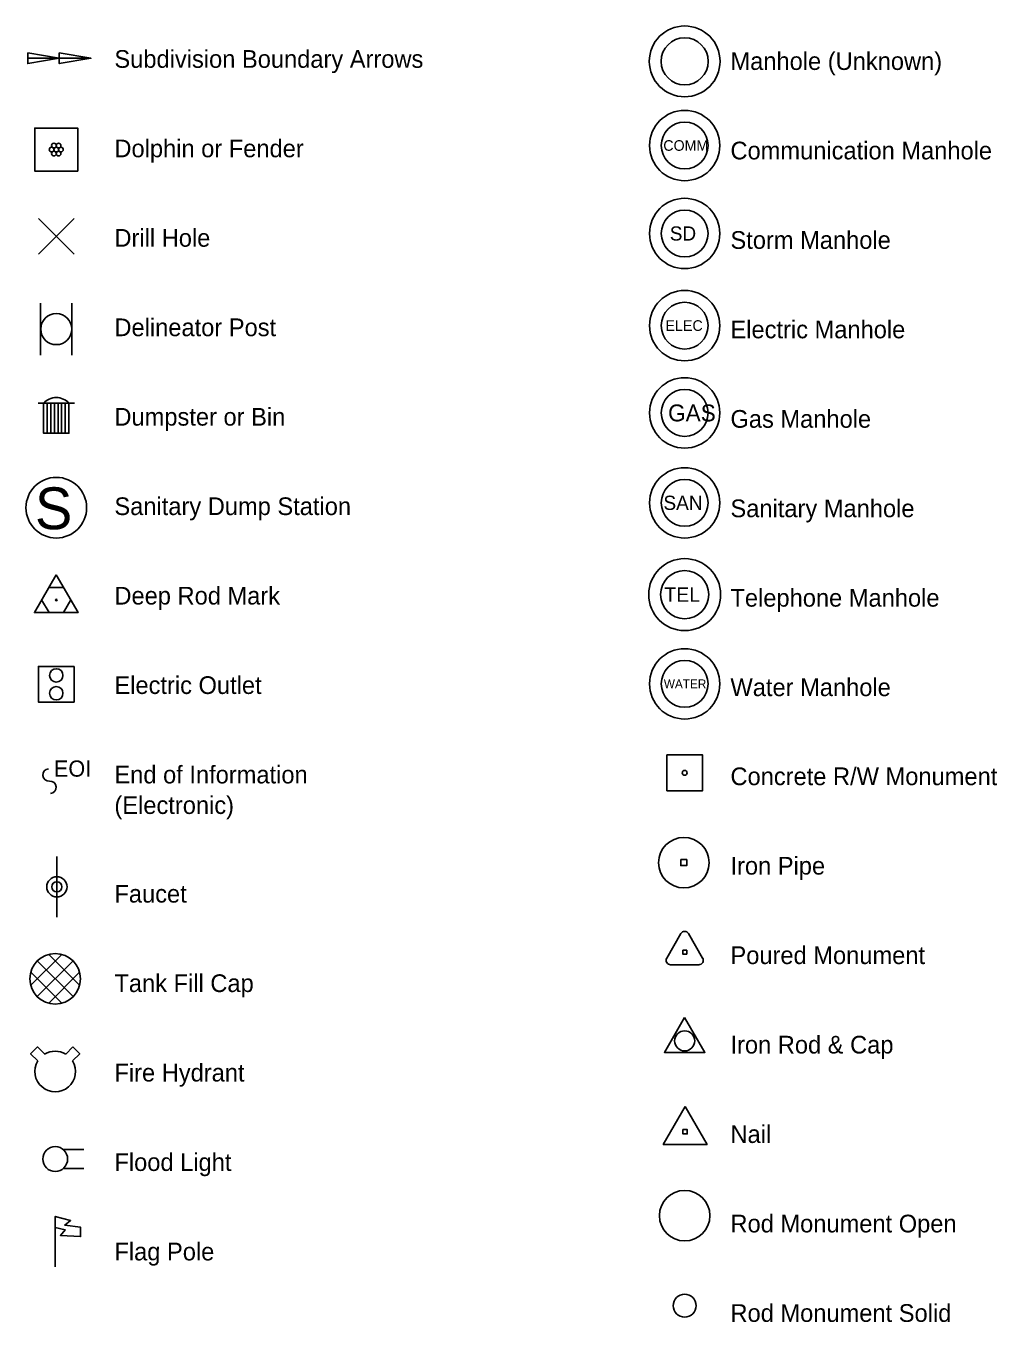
# Model space of a CAD drawing. Extents: x -371 to 730, y -9 to 425.
# Drawn here: x -370.9 to -274.8, y 166.6 to 294.8 of the extents above; entities that cross this region are included whole.
import ezdxf

# ---------------------------------------------------------------- set-up
doc = ezdxf.new("R2010")
doc.units = 0
for name, color, linetype in [('DelineatorPost_ep', 7, 'Continuous'), ('Dolphins_ep', 7, 'Continuous'), ('FireHydrant_ep', 7, 'Continuous'), ('FloodLight_ep', 7, 'Continuous'), ('ManholeCover_ep', 7, 'Continuous'), ('ManholeCovUnk_ep', 7, 'Continuous'), ('ManholeCovW_ep', 7, 'Continuous'), ('ManholeElec_ep', 7, 'Continuous'), ('ManholeGas_ep', 7, 'Continuous'), ('ManholeSS_ep', 7, 'Continuous'), ('ManholeSW_ep', 7, 'Continuous'), ('ManholeTel_ep', 7, 'Continuous'), ('MiscEquip_ep', 7, 'Continuous'), ('Monument_ep', 7, 'Continuous'), ('PowerElecOut_ep', 7, 'Continuous'), ('SanitaryDumpSta_ep', 7, 'Continuous'), ('SU_Misc_ep', 7, 'Continuous'), ('TankUG_ep', 7, 'Continuous'), ('Trash_ep', 7, 'Continuous'), ('WaterMisc_ep', 7, 'Continuous')]:
    doc.layers.add(name, color=color, linetype=linetype)

# ---------------------------------------------------------------- blocks, each defined once
blk = doc.blocks.new('DblArrow')
blk.add_line((0, 0), (-1, 0))
for points in [[(-1, 0.083), (-0.5, 0), (-1, -0.084)], [(-0.5, 0.083), (0, 0), (-0.5, -0.084)]]:
    blk.add_lwpolyline(points, close=True)
blk = doc.blocks.new('EOI')
at = {"layer": 'SU_Misc_ep'}
for centre, start, end in [((-0.05, 0.61), 95, 275), ((0.05, -0.61), 275, 95)]:
    blk.add_arc(centre, 0.613, start, end, dxfattribs=at)
blk.add_text('EOI', height=1.6, dxfattribs=at).set_placement((0.44, 0.44))

msp = doc.modelspace()

# ---------------------------------------------------------------- linework, layer by layer
for centre in [(-368.34, 282.61), (-368.11, 283.01), (-368.11, 282.21), (-367.64, 283.01), (-367.64, 282.21), (-367.41, 282.61)]:
    msp.add_circle(centre, 0.231)
at = {"layer": 'DelineatorPost_ep'}
for p, q in [((-369.42, 262.28), (-369.42, 267.42)), ((-366.33, 262.28), (-366.33, 267.42))]:
    msp.add_line(p, q, dxfattribs=at)
msp.add_circle((-367.87, 264.85), 1.54, dxfattribs=at)
at = {"layer": 'Dolphins_ep'}
msp.add_lwpolyline([(-365.75, 280.49), (-365.75, 284.73), (-370, 284.73), (-370, 280.49)], close=True, dxfattribs=at)
msp.add_circle((-367.87, 282.61), 0.231, dxfattribs=at)
at = {"layer": 'FireHydrant_ep'}
for points in [[(-369.02, 193.12), (-369.74, 193.83), (-370.41, 193.16), (-369.69, 192.44)], [(-366.22, 193.83), (-366.93, 193.12)], [(-366.26, 192.44), (-365.55, 193.16), (-366.22, 193.83)]]:
    msp.add_lwpolyline(points, dxfattribs=at)
for start, end in [(148.7002, 31.2998), (58.7002, 121.2998)]:
    msp.add_arc((-367.98, 191.4), 2.01, start, end, dxfattribs=at)
at = {"layer": 'FloodLight_ep'}
for p, q in [((-367.18, 183.68), (-365.13, 183.68)), ((-367.18, 181.81), (-365.13, 181.81))]:
    msp.add_line(p, q, dxfattribs=at)
msp.add_circle((-367.98, 182.74), 1.23, dxfattribs=at)
at = {"layer": 'ManholeCover_ep'}
for radius in [3.48, 2.32]:
    msp.add_circle((-305.7, 283.01), radius, dxfattribs=at)
at = {"layer": 'ManholeCovUnk_ep'}
for radius in [3.5, 2.33]:
    msp.add_circle((-305.7, 291.34), radius, dxfattribs=at)
at = {"layer": 'ManholeCovW_ep'}
for radius in [3.48, 2.32]:
    msp.add_circle((-305.7, 229.75), radius, dxfattribs=at)
at = {"layer": 'ManholeElec_ep'}
for radius in [3.48, 2.32]:
    msp.add_circle((-305.7, 265.19), radius, dxfattribs=at)
at = {"layer": 'ManholeGas_ep'}
for radius in [3.48, 2.32]:
    msp.add_circle((-305.7, 256.56), radius, dxfattribs=at)
at = {"layer": 'ManholeSS_ep'}
for radius in [3.48, 2.32]:
    msp.add_circle((-305.7, 247.66), radius, dxfattribs=at)
at = {"layer": 'ManholeSW_ep'}
for radius in [3.48, 2.32]:
    msp.add_circle((-305.7, 274.31), radius, dxfattribs=at)
at = {"layer": 'ManholeTel_ep'}
for radius in [3.56, 2.38]:
    msp.add_circle((-305.7, 238.58), radius, dxfattribs=at)
at = {"layer": 'MiscEquip_ep'}
msp.add_lwpolyline([(-367.98, 172.06), (-367.98, 177.06), (-366.45, 176.66), (-367.04, 176.2), (-365.48, 176), (-365.46, 175.07), (-367.46, 175.19), (-366.99, 175.72), (-367.98, 175.98)], dxfattribs=at)
at = {"layer": 'Monument_ep'}
for p, q in [((-369.63, 272.27), (-366.11, 275.8)), ((-366.11, 272.27), (-369.63, 275.8)), ((-367.15, 239.3), (-368.6, 239.3)), ((-369.32, 238.05), (-368.59, 236.8)), ((-367.16, 236.8), (-366.43, 238.06))]:
    msp.add_line(p, q, dxfattribs=at)
for points in [[(-367.87, 240.55), (-370.04, 236.8), (-365.71, 236.8)], [(-307.46, 222.72), (-307.46, 219.18), (-303.93, 219.18), (-303.93, 222.72)], [(-306.08, 212.36), (-306.08, 211.77), (-305.49, 211.77), (-305.49, 212.36)], [(-305.89, 203.4), (-305.89, 203.01), (-305.5, 203.01), (-305.5, 203.4)], [(-305.7, 196.74), (-307.7, 193.28), (-303.7, 193.28)], [(-305.66, 187.94), (-307.82, 184.19), (-303.49, 184.19)], [(-305.88, 185.66), (-305.88, 185.22), (-305.44, 185.22), (-305.44, 185.66)]]:
    msp.add_lwpolyline(points, close=True, dxfattribs=at)
for points in [[(-306.08, 205.04), (-307.48, 202.62)], [(-303.92, 202.62), (-305.31, 205.04)], [(-307.09, 201.96), (-304.3, 201.96)]]:
    msp.add_lwpolyline(points, dxfattribs=at)
for centre, radius in [((-367.87, 238.05), 0.0873), ((-305.7, 220.95), 0.236), ((-305.78, 212.06), 2.5), ((-305.7, 194.43), 0.99), ((-305.7, 177.14), 2.5)]:
    msp.add_circle(centre, radius, dxfattribs=at)
for centre, radius, start, end in [((-305.7, 204.82), 0.444, 30, 150), ((-307.09, 202.4), 0.444, 150, 270), ((-304.3, 202.4), 0.444, 270, 30), ((-305.7, 168.23), 1.13, 0, 180), ((-305.7, 168.23), 1.13, 180, 0)]:
    msp.add_arc(centre, radius, start, end, dxfattribs=at)
at = {"layer": 'PowerElecOut_ep'}
msp.add_lwpolyline([(-366.11, 231.48), (-369.64, 231.48), (-369.64, 227.94), (-366.11, 227.94)], close=True, dxfattribs=at)
for centre in [(-367.87, 230.59), (-367.87, 228.82)]:
    msp.add_circle(centre, 0.663, dxfattribs=at)
at = {"layer": 'SanitaryDumpSta_ep'}
msp.add_circle((-367.87, 247.18), 3, dxfattribs=at)
at = {"layer": 'TankUG_ep'}
for p, q in [((-370.39, 199.93), (-367.33, 202.99)), ((-365.56, 199.93), (-368.62, 202.99)), ((-366.21, 198.81), (-369.75, 202.34)), ((-369.75, 198.81), (-366.21, 202.34)), ((-367.33, 198.16), (-370.39, 201.22)), ((-368.62, 198.16), (-365.56, 201.22))]:
    msp.add_line(p, q, dxfattribs=at)
msp.add_circle((-367.98, 200.57), 2.5, dxfattribs=at)
at = {"layer": 'Trash_ep'}
for points in [[(-369.67, 257.51), (-366.07, 257.51)], [(-366.62, 257.51), (-366.62, 254.55), (-369.13, 254.55), (-369.13, 257.51)], [(-368.77, 254.55), (-368.77, 257.51)], [(-368.41, 254.55), (-368.41, 257.51)], [(-368.05, 254.55), (-368.05, 257.51)], [(-367.7, 254.55), (-367.7, 257.51)], [(-367.34, 254.55), (-367.34, 257.51)], [(-366.98, 254.55), (-366.98, 257.51)]]:
    msp.add_lwpolyline(points, dxfattribs=at)
msp.add_arc((-367.87, 256.41), 1.67, 41.1562, 138.8438, dxfattribs=at)
at = {"layer": 'WaterMisc_ep'}
msp.add_line((-367.81, 206.67), (-367.81, 212.67), dxfattribs=at)
for radius in [1, 0.5]:
    msp.add_circle((-367.81, 209.67), radius, dxfattribs=at)

# ---------------------------------------------------------------- block references
at = {"xscale": 6.25, "yscale": 6.25}
msp.add_blockref('DblArrow', (-364.45, 291.65), dxfattribs=at)
msp.add_blockref('EOI', (-368.54, 220.13))

# ---------------------------------------------------------------- texts
for s, p in [('Subdivision Boundary Arrows', (-362.12, 290.7)), ('Manhole (Unknown)', (-301.17, 290.49)), ('Dolphin or Fender', (-362.12, 281.85)), ('Communication Manhole', (-301.17, 281.64)), ('Drill Hole', (-362.12, 273)), ('Storm Manhole', (-301.17, 272.79)), ('Delineator Post', (-362.12, 264.15)), ('Electric Manhole', (-301.17, 263.94)), ('Dumpster or Bin', (-362.12, 255.3)), ('Gas Manhole', (-301.17, 255.09)), ('Sanitary Dump Station', (-362.12, 246.45)), ('Sanitary Manhole', (-301.17, 246.24)), ('Deep Rod Mark', (-362.12, 237.6)), ('Telephone Manhole', (-301.17, 237.39)), ('Electric Outlet', (-362.12, 228.75)), ('Water Manhole', (-301.17, 228.54)), ('End of Information ', (-362.12, 219.9)), ('Concrete R/W Monument', (-301.17, 219.73)), ('(Electronic)', (-362.12, 216.88)), ('Iron Pipe', (-301.17, 210.88)), ('Faucet', (-362.12, 208.11)), ('Poured Monument', (-301.17, 202.03)), ('Tank Fill Cap', (-362.12, 199.26)), ('Iron Rod & Cap', (-301.17, 193.18)), ('Fire Hydrant', (-362.12, 190.41)), ('Nail', (-301.17, 184.33)), ('Flood Light', (-362.12, 181.56)), ('Rod Monument Open', (-301.17, 175.48)), ('Flag Pole', (-362.12, 172.71)), ('Rod Monument Solid', (-301.17, 166.63))]:
    msp.add_text(s, height=1.75).set_placement(p)
at = {"layer": 'ManholeCover_ep'}
msp.add_text('COMM', height=1.05, dxfattribs=at).set_placement((-307.81, 282.49))
at = {"layer": 'ManholeCovW_ep'}
msp.add_text('WATER', height=0.87, dxfattribs=at).set_placement((-307.76, 229.32))
at = {"layer": 'ManholeElec_ep'}
msp.add_text('ELEC', height=1.057, dxfattribs=at).set_placement((-307.6, 264.67))
at = {"layer": 'ManholeGas_ep'}
msp.add_text('GAS', height=1.67, dxfattribs=at).set_placement((-307.34, 255.72))
at = {"layer": 'ManholeSS_ep'}
msp.add_text('SAN', height=1.408, dxfattribs=at).set_placement((-307.8, 246.96))
at = {"layer": 'ManholeSW_ep'}
msp.add_text('SD', height=1.401, dxfattribs=at).set_placement((-307.17, 273.61))
at = {"layer": 'ManholeTel_ep'}
msp.add_text('TEL', height=1.441, dxfattribs=at).set_placement((-307.71, 237.87))
at = {"layer": 'SanitaryDumpSta_ep'}
msp.add_text('S', height=4.14, dxfattribs=at).set_placement((-369.98, 245.05))

doc.saveas('drawing.dxf')
